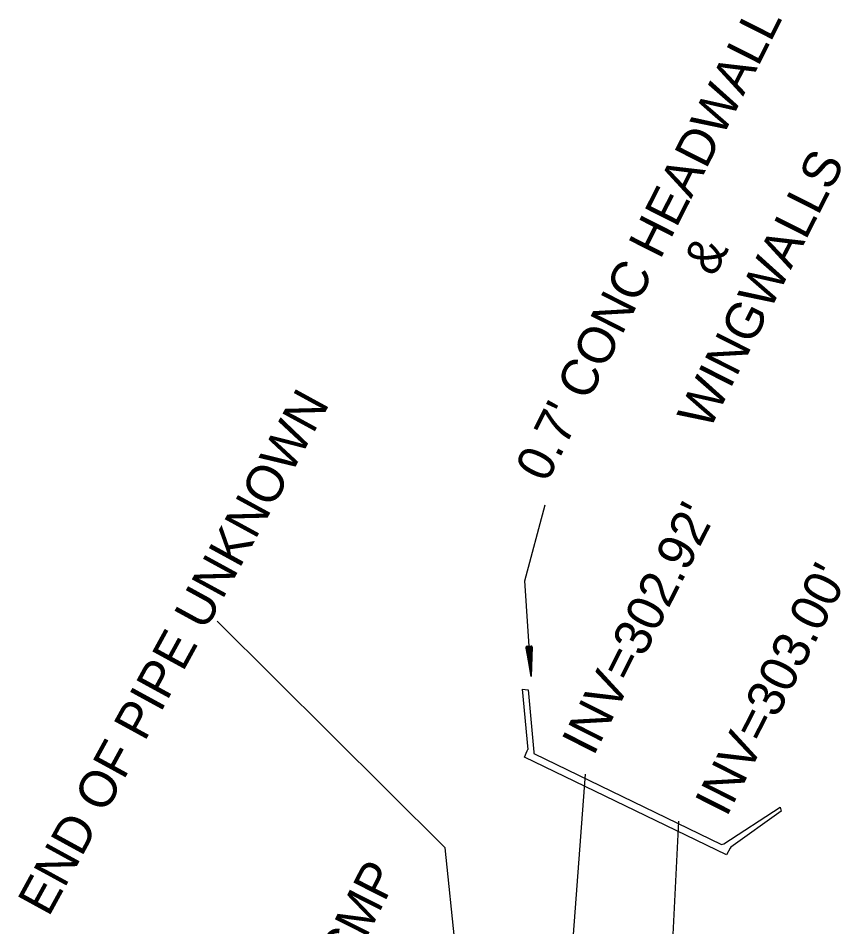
# Model space of a CAD drawing. Extents: x 1975859 to 1978323, y 778892 to 782836.
# Drawn here: x 1977899.9 to 1977989.2, y 782672.2 to 782770.8 of the extents above; entities that cross this region are included whole.
import ezdxf

# ---------------------------------------------------------------- set-up
doc = ezdxf.new("R2010")
doc.units = 0
for name, color, linetype in [('Exist Structure Major Bridge WW', 7, 'Continuous'), ('Exist Structure Major Bridge WW Text', 7, 'Continuous'), ('Exist Structure Minor Pipes CMP 15 Inch Invert', 7, 'Continuous'), ('Exist Structure Minor Pipes CMP 15 Inch SizeText', 7, 'Continuous'), ('Exist Structure Minor Pipes CMP 84 Inch', 7, 'Continuous'), ('Exist Structure Minor Pipes CMP 84 Inch Invert', 7, 'Continuous')]:
    doc.layers.add(name, color=color, linetype=linetype)

msp = doc.modelspace()

# ---------------------------------------------------------------- linework, layer by layer
at = {"layer": 'Exist Structure Major Bridge WW'}
for p, q in [((1977954.577, 782698.008), (1977955.19, 782691.462)), ((1977954.577, 782698.008), (1977955.213, 782697.934)), ((1977955.213, 782697.934), (1977955.843, 782691.192)), ((1977954.842, 782690.638), (1977955.119, 782691.323)), ((1977955.119, 782691.323), (1977955.19, 782691.462)), ((1977955.843, 782691.192), (1977955.833, 782691.038)), ((1977976.723, 782680.046), (1977954.842, 782690.638)), ((1977955.833, 782691.038), (1977976.206, 782681.15)), ((1977976.459, 782681.223), (1977982.562, 782685.196)), ((1977982.562, 782685.196), (1977982.653, 782684.771)), ((1977982.653, 782684.771), (1977977.216, 782680.858)), ((1977976.206, 782681.15), (1977976.459, 782681.223)), ((1977977.122, 782680.755), (1977976.723, 782680.046)), ((1977977.216, 782680.858), (1977977.122, 782680.755))]:
    msp.add_line(p, q, dxfattribs=at)
at = {"layer": 'Exist Structure Major Bridge WW Text'}
for p, q in [((1977954.855, 782709.758), (1977957.066, 782718.028)), ((1977955.549, 782699.403), (1977954.855, 782709.758)), ((1977955.062, 782702.694), (1977955.594, 782702.73)), ((1977955.349, 782702.392), (1977955.113, 782702.652)), ((1977955.349, 782702.392), (1977955.164, 782702.701)), ((1977955.349, 782702.392), (1977955.27, 782702.708)), ((1977955.349, 782702.392), (1977955.475, 782702.72)), ((1977955.349, 782702.392), (1977955.386, 782702.718)), ((1977955.548, 782702.681), (1977955.349, 782702.392))]:
    msp.add_line(p, q, dxfattribs=at)
for points in [[(1977955.062, 782702.694), (1977954.985, 782702.458), (1977955.549, 782699.403), (1977955.701, 782702.506), (1977955.594, 782702.73)], [(1977955.647, 782702.617), (1977955.549, 782699.403), (1977955.024, 782702.576)], [(1977955.13, 782702.545), (1977955.549, 782699.403), (1977955.062, 782702.694), (1977955.113, 782702.652), (1977955.13, 782702.545), (1977955.349, 782702.392), (1977955.549, 782702.573), (1977955.548, 782702.681), (1977955.594, 782702.73), (1977955.549, 782699.403), (1977955.549, 782702.573)], [(1977955.548, 782699.576), (1977955.543, 782699.497), (1977955.525, 782699.589), (1977955.512, 782699.682), (1977955.536, 782699.59), (1977955.549, 782699.67), (1977955.549, 782699.765), (1977955.531, 782699.683), (1977955.5, 782699.774), (1977955.488, 782699.867), (1977955.524, 782699.777), (1977955.549, 782699.858), (1977955.548, 782699.951), (1977955.518, 782699.87), (1977955.475, 782699.959), (1977955.463, 782700.053), (1977955.512, 782699.963), (1977955.548, 782700.045), (1977955.548, 782700.139), (1977955.505, 782700.057), (1977955.451, 782700.145), (1977955.438, 782700.238), (1977955.499, 782700.15), (1977955.548, 782700.232), (1977955.548, 782700.325), (1977955.493, 782700.243), (1977955.426, 782700.331), (1977955.414, 782700.424), (1977955.487, 782700.337), (1977955.548, 782700.419), (1977955.549, 782700.513), (1977955.48, 782700.431), (1977955.401, 782700.517), (1977955.389, 782700.609), (1977955.474, 782700.524), (1977955.548, 782700.607), (1977955.549, 782700.7), (1977955.468, 782700.618), (1977955.377, 782700.702), (1977955.365, 782700.795), (1977955.461, 782700.711), (1977955.548, 782700.794), (1977955.549, 782700.888), (1977955.455, 782700.804), (1977955.352, 782700.888), (1977955.34, 782700.981), (1977955.449, 782700.898), (1977955.549, 782700.981), (1977955.548, 782701.075), (1977955.443, 782700.991), (1977955.327, 782701.074), (1977955.315, 782701.166), (1977955.437, 782701.084), (1977955.548, 782701.168), (1977955.549, 782701.262), (1977955.43, 782701.178), (1977955.302, 782701.259), (1977955.29, 782701.352), (1977955.424, 782701.271), (1977955.549, 782701.355), (1977955.549, 782701.449), (1977955.418, 782701.365), (1977955.277, 782701.445), (1977955.265, 782701.537), (1977955.411, 782701.458), (1977955.548, 782701.543), (1977955.549, 782701.636), (1977955.405, 782701.552), (1977955.253, 782701.63), (1977955.241, 782701.723), (1977955.39, 782701.645), (1977955.549, 782701.73), (1977955.549, 782701.824), (1977955.393, 782701.738), (1977955.228, 782701.816), (1977955.216, 782701.908), (1977955.387, 782701.832), (1977955.549, 782701.917), (1977955.548, 782702.011), (1977955.38, 782701.925), (1977955.204, 782702.002), (1977955.191, 782702.094), (1977955.374, 782702.019), (1977955.549, 782702.105), (1977955.548, 782702.198), (1977955.368, 782702.112), (1977955.179, 782702.187), (1977955.167, 782702.28), (1977955.362, 782702.206), (1977955.548, 782702.292), (1977955.548, 782702.385), (1977955.355, 782702.299), (1977955.154, 782702.373), (1977955.142, 782702.466), (1977955.349, 782702.392), (1977955.548, 782702.479)]]:
    msp.add_lwpolyline(points, dxfattribs=at)
at = {"layer": 'Exist Structure Minor Pipes CMP 15 Inch Invert'}
for p, q in [((1977946.22, 782680.796), (1977921.496, 782705.39)), ((1977947.621, 782667.54), (1977946.224, 782680.79))]:
    msp.add_line(p, q, dxfattribs=at)
at = {"layer": 'Exist Structure Minor Pipes CMP 84 Inch'}
for p, q in [((1977961.421, 782688.777), (1977956.624, 782625.902)), ((1977971.523, 782683.692), (1977968.272, 782619.938))]:
    msp.add_line(p, q, dxfattribs=at)

# ---------------------------------------------------------------- texts
at = {"layer": 'Exist Structure Major Bridge WW Text'}
for s, p in [("0.7' CONC HEADWALL", (1977957.245, 782720.278)), ('WINGWALLS', (1977974.833, 782725.969)), ('&', (1977975.417, 782742.633))]:
    msp.add_text(s, height=4, rotation=63.11985, dxfattribs=at).set_placement(p)
at = {"layer": 'Exist Structure Minor Pipes CMP 15 Inch Invert'}
msp.add_text('END OF PIPE UNKNOWN', height=4, rotation=61.32463, dxfattribs=at).set_placement((1977903.236, 782673.204))
at = {"layer": 'Exist Structure Minor Pipes CMP 15 Inch SizeText'}
msp.add_text('15" CMP', height=4, rotation=63.11985, dxfattribs=at).set_placement((1977931.67, 782659.086))
at = {"layer": 'Exist Structure Minor Pipes CMP 84 Inch Invert'}
for s, p in [("INV=302.92'", (1977962.299, 782690.637)), ("INV=303.00'", (1977976.731, 782684.024))]:
    msp.add_text(s, height=4, rotation=63.11985, dxfattribs=at).set_placement(p)

doc.saveas('drawing.dxf')
